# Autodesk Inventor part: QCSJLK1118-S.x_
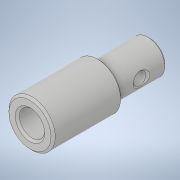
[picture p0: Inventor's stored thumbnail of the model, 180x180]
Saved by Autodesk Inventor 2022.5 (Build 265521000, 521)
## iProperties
Created: 2021-08
Part Number: QCSJLK1118-S.x_
Material: 一般
Document SubType Name: Modeling
Designer: ImaoCorp
Density: 1 g/cm^3
Appearance: 既定
Sending System: SOLIDWORKS 2019-2019304
MC: AMD64
MC_MODEL: Intel64 Family 6 Model 60 Stepping 3, GenuineIntel
OS: Windows_NT
FRU: Parasolid Version 31.0, build 290,  9- 1-2019
FORMAT: text
GUISE: transmit
KEY: QCSJLK1118-S
FILE: QCSJLK1118-S.x_t
DATE: Wed Aug 11 15:10:28 2021
Author: ImaoCorp
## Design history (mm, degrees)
feature "Base1"
node "ソリッド1"
